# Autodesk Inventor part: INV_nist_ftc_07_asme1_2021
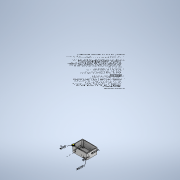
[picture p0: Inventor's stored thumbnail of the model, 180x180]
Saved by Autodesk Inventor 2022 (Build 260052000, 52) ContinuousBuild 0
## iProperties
Created: 2020-11
Part Number: INV_nist_ftc_07_asme1_2021
Material: Generic
Document SubType Name: Modeling
Designer: lik
Density: 1 g/cm^3
Appearance: Default
Title: C:\Users\lik\Desktop\MTFinal\INV_nist_ftc_07_asme1_2021.stp
Author: lik
Sending System: Autodesk Inventor 2022
Preprocessor: ST-DEVELOPER v18.1
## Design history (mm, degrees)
node "Label"
node "Label:1"
node "Datum"
node "Note"
node "Position"
node "Datum:1"
node "Note:1"
node "Perpendicularity"
node "Label:2"
node "Datum:2"
node "Profile of surface"
node "Note:2"
node "Position:1"
node "Note:3"
node "Position:2"
node "General note"
node "Label:3"
node "Datum:3"
node "Profile of surface:1"
node "Diameter dimension"
node "Position:3"
node "Diameter dimension:1"
node "Position:4"
node "Diameter dimension:2"
node "Position:5"
node "General tolerance"
node "Note:4"
node "Position:6"
node "Label:4"
node "Datum:4"
node "Profile of surface:2"
node "Label:5"
node "Profile of surface:3"
node "Diameter dimension:3"
node "Position:7"
node "Label:6"
node "Profile of surface:4"
node "Profile of surface:5"
node "Radial dimension"
node "Repaired Geometry1"
  sketch "Sketch10"
feature "Solid1"
body "Solid2"
